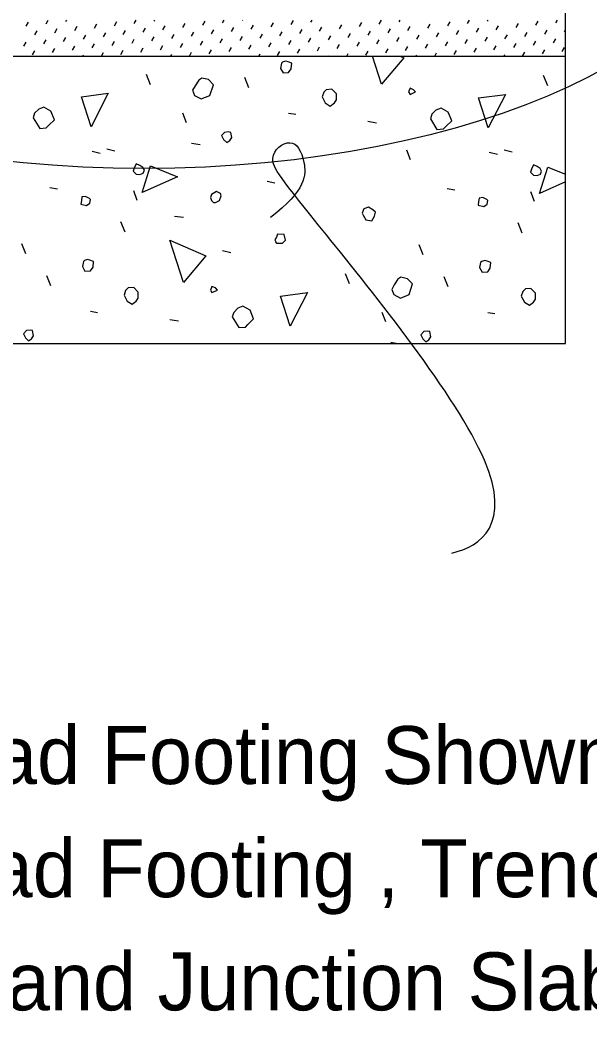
# Model space of a CAD drawing. Extents: x 120631.6 to 120706.2, y 120663.5 to 120716.4.
# Drawn here: x 120668.23 to 120670.212, y 120691.041 to 120694.546 of the extents above; entities that cross this region are included whole.
import ezdxf

# ---------------------------------------------------------------- set-up
doc = ezdxf.new("R2010")
doc.units = 0
for name, color, linetype in [('Dimension', 7, 'Continuous'), ('Miscellaneous', 7, 'Continuous'), ('TextStructures', 7, 'Continuous'), ('TrafBarrierConc', 7, 'Continuous')]:
    doc.layers.add(name, color=color, linetype=linetype)

msp = doc.modelspace()

# ---------------------------------------------------------------- linework, layer by layer
at = {"layer": 'Dimension'}
msp.add_ellipse((120668.6608, 120695.0005), major_axis=(2.0883, 0), ratio=0.464675, dxfattribs=at)
msp.add_open_spline([(120669.7314, 120692.6924), (120669.8349, 120692.715), (120670.0444, 120692.8737), (120669.1629, 120693.9627), (120669.0781, 120694.0699), (120669.1763, 120694.1458), (120669.2254, 120694.0654), (120669.2254, 120693.9538), (120669.1004, 120693.86)], degree=3, dxfattribs=at)
at = {"layer": 'Miscellaneous'}
for p, q in [((120668.2507, 120694.5249), (120668.2588, 120694.5389)), ((120668.3199, 120694.533), (120668.3274, 120694.546)), ((120668.389, 120694.5411), (120668.3919, 120694.546)), ((120668.4196, 120694.5106), (120668.4277, 120694.5246)), ((120668.4887, 120694.5187), (120668.4968, 120694.5327)), ((120668.5579, 120694.5268), (120668.566, 120694.5408)), ((120668.627, 120694.5349), (120668.6335, 120694.546)), ((120668.6962, 120694.543), (120668.698, 120694.546)), ((120668.7267, 120694.5124), (120668.7348, 120694.5264)), ((120668.7959, 120694.5205), (120668.804, 120694.5345)), ((120668.8651, 120694.5286), (120668.8732, 120694.5426)), ((120668.9342, 120694.5368), (120668.9396, 120694.546)), ((120668.9648, 120694.5062), (120668.9729, 120694.5202)), ((120669.0034, 120694.5449), (120669.0041, 120694.546)), ((120669.0339, 120694.5143), (120669.042, 120694.5283)), ((120669.1031, 120694.5224), (120669.1112, 120694.5364)), ((120669.1723, 120694.5305), (120669.1804, 120694.5445)), ((120669.2414, 120694.5386), (120669.2457, 120694.546)), ((120669.2719, 120694.5081), (120669.28, 120694.5221)), ((120669.3411, 120694.5162), (120669.3492, 120694.5302)), ((120669.4103, 120694.5243), (120669.4184, 120694.5383)), ((120669.4794, 120694.5324), (120669.4873, 120694.546)), ((120669.5486, 120694.5405), (120669.5518, 120694.546)), ((120669.5791, 120694.51), (120669.5872, 120694.524)), ((120669.6483, 120694.5181), (120669.6564, 120694.5321)), ((120669.7175, 120694.5262), (120669.7256, 120694.5402)), ((120669.7866, 120694.5343), (120669.7934, 120694.546)), ((120669.8558, 120694.5424), (120669.8579, 120694.546)), ((120669.8863, 120694.5119), (120669.8944, 120694.5258)), ((120669.9555, 120694.52), (120669.9636, 120694.534)), ((120670.0246, 120694.5281), (120670.0327, 120694.5421)), ((120670.0938, 120694.5362), (120670.0995, 120694.546)), ((120668.2812, 120694.4944), (120668.2893, 120694.5084)), ((120668.3504, 120694.5025), (120668.3585, 120694.5165)), ((120668.3809, 120694.4719), (120668.389, 120694.4859)), ((120668.4501, 120694.48), (120668.4582, 120694.494)), ((120668.5192, 120694.4881), (120668.5273, 120694.5021)), ((120668.5884, 120694.4962), (120668.5965, 120694.5102)), ((120668.6576, 120694.5043), (120668.6657, 120694.5183)), ((120668.6881, 120694.4738), (120668.6962, 120694.4878)), ((120668.7573, 120694.4819), (120668.7654, 120694.4959)), ((120668.8264, 120694.49), (120668.8345, 120694.504)), ((120668.8956, 120694.4981), (120668.9037, 120694.5121)), ((120668.9953, 120694.4757), (120669.0034, 120694.4897)), ((120669.0645, 120694.4838), (120669.0726, 120694.4978)), ((120669.1336, 120694.4919), (120669.1417, 120694.5059)), ((120669.2028, 120694.5), (120669.2109, 120694.514)), ((120669.3025, 120694.4776), (120669.3106, 120694.4916)), ((120669.3716, 120694.4857), (120669.3797, 120694.4997)), ((120669.4408, 120694.4938), (120669.4489, 120694.5078)), ((120669.51, 120694.5019), (120669.5181, 120694.5159)), ((120669.5405, 120694.4713), (120669.5486, 120694.4853)), ((120669.6097, 120694.4794), (120669.6178, 120694.4934)), ((120669.6788, 120694.4875), (120669.6869, 120694.5015)), ((120669.748, 120694.4957), (120669.7561, 120694.5096)), ((120669.8172, 120694.5038), (120669.8253, 120694.5177)), ((120669.8477, 120694.4732), (120669.8558, 120694.4872)), ((120669.9168, 120694.4813), (120669.925, 120694.4953)), ((120669.986, 120694.4894), (120669.9941, 120694.5034)), ((120670.0552, 120694.4975), (120670.0633, 120694.5115)), ((120670.1243, 120694.5056), (120670.1273, 120694.5107)), ((120668.2426, 120694.4557), (120668.2507, 120694.4697)), ((120668.3118, 120694.4638), (120668.3199, 120694.4778)), ((120668.4114, 120694.4414), (120668.4196, 120694.4554)), ((120668.4806, 120694.4495), (120668.4887, 120694.4635)), ((120668.5498, 120694.4576), (120668.5579, 120694.4716)), ((120668.6189, 120694.4657), (120668.627, 120694.4797)), ((120668.6495, 120694.4352), (120668.6576, 120694.4492)), ((120668.7186, 120694.4433), (120668.7267, 120694.4573)), ((120668.7878, 120694.4514), (120668.7959, 120694.4654)), ((120668.857, 120694.4595), (120668.8651, 120694.4735)), ((120668.9261, 120694.4676), (120668.9342, 120694.4816)), ((120668.9567, 120694.4371), (120668.9648, 120694.4511)), ((120669.0258, 120694.4452), (120669.0339, 120694.4592)), ((120669.095, 120694.4533), (120669.1031, 120694.4673)), ((120669.1641, 120694.4614), (120669.1723, 120694.4754)), ((120669.2333, 120694.4695), (120669.2414, 120694.4835)), ((120669.2638, 120694.4389), (120669.2719, 120694.4529)), ((120669.333, 120694.447), (120669.3411, 120694.461)), ((120669.4022, 120694.4551), (120669.4103, 120694.4691)), ((120669.4713, 120694.4632), (120669.4794, 120694.4772)), ((120669.571, 120694.4408), (120669.5791, 120694.4548)), ((120669.6402, 120694.4489), (120669.6483, 120694.4629)), ((120669.7094, 120694.457), (120669.7175, 120694.471)), ((120669.7785, 120694.4651), (120669.7866, 120694.4791)), ((120669.8782, 120694.4427), (120669.8863, 120694.4567)), ((120669.9474, 120694.4508), (120669.9555, 120694.4648)), ((120670.0165, 120694.4589), (120670.0246, 120694.4729)), ((120670.0857, 120694.467), (120670.0938, 120694.481)), ((120670.1162, 120694.4365), (120670.1243, 120694.4505)), ((120668.2731, 120694.4252), (120668.2812, 120694.4392)), ((120668.3423, 120694.4333), (120668.3504, 120694.4473)), ((120668.4478, 120694.421), (120668.4501, 120694.4249)), ((120668.5123, 120694.421), (120668.5192, 120694.433)), ((120668.5803, 120694.4271), (120668.5884, 120694.4411)), ((120668.7539, 120694.421), (120668.7573, 120694.4267)), ((120668.8184, 120694.421), (120668.8264, 120694.4348)), ((120668.8875, 120694.429), (120668.8956, 120694.4429)), ((120669.06, 120694.421), (120669.0645, 120694.4286)), ((120669.1255, 120694.4227), (120669.1336, 120694.4367)), ((120669.1947, 120694.4308), (120669.2028, 120694.4448)), ((120669.3017, 120694.421), (120669.3025, 120694.4224)), ((120669.3661, 120694.421), (120669.3716, 120694.4305)), ((120669.4327, 120694.4246), (120669.4408, 120694.4386)), ((120669.5019, 120694.4327), (120669.51, 120694.4467)), ((120669.6078, 120694.421), (120669.6097, 120694.4243)), ((120669.6722, 120694.421), (120669.6788, 120694.4324)), ((120669.7399, 120694.4265), (120669.748, 120694.4405)), ((120669.8091, 120694.4346), (120669.8172, 120694.4486)), ((120669.9139, 120694.421), (120669.9168, 120694.4262)), ((120669.9783, 120694.421), (120669.986, 120694.4343)), ((120670.0471, 120694.4284), (120670.0552, 120694.4424)), ((120668.6831, 120694.3216), (120668.6689, 120694.357)), ((120669.026, 120694.311), (120669.0119, 120694.3464)), ((120670.0655, 120694.3181), (120670.0513, 120694.3534)), ((120668.8086, 120694.189), (120668.7962, 120694.2226)), ((120669.1639, 120694.2226), (120669.1887, 120694.2191)), ((120669.4397, 120694.1943), (120669.4697, 120694.189)), ((120668.5311, 120694.0989), (120668.5593, 120694.0918)), ((120668.8263, 120694.1183), (120668.8563, 120694.113)), ((120668.4798, 120694.09), (120668.5081, 120694.083)), ((120669.5882, 120694.06), (120669.5758, 120694.0936)), ((120669.8622, 120694.0865), (120669.8905, 120694.0794)), ((120669.9135, 120694.0953), (120669.9417, 120694.0883)), ((120668.3331, 120693.9645), (120668.3596, 120693.9592)), ((120669.0897, 120693.9857), (120669.1162, 120693.9804)), ((120669.7155, 120693.961), (120669.742, 120693.9557)), ((120668.6371, 120693.9186), (120668.6248, 120693.9521)), ((120670.0195, 120693.915), (120670.0071, 120693.9486)), ((120668.7662, 120693.8638), (120668.798, 120693.8602)), ((120668.5947, 120693.809), (120668.5806, 120693.8443)), ((120669.9771, 120693.8054), (120669.963, 120693.8408)), ((120668.25, 120693.7329), (120668.2358, 120693.7683)), ((120669.6324, 120693.7294), (120669.6182, 120693.7648)), ((120668.9341, 120693.7453), (120668.9624, 120693.7382)), ((120668.3366, 120693.6216), (120668.3225, 120693.6569)), ((120669.3761, 120693.6286), (120669.3619, 120693.664)), ((120669.719, 120693.618), (120669.7049, 120693.6534)), ((120668.4745, 120693.5332), (120668.4992, 120693.5296)), ((120668.7503, 120693.5049), (120668.7803, 120693.4996)), ((120669.5016, 120693.4961), (120669.4892, 120693.5296)), ((120669.8569, 120693.5296), (120669.8816, 120693.5261)), ((120669.5192, 120693.4254), (120669.5438, 120693.421))]:
    msp.add_line(p, q, dxfattribs=at)
for points in [[(120669.4874, 120694.3234), (120669.4557, 120694.421)], [(120669.5521, 120694.421), (120669.5652, 120694.4153), (120669.4874, 120694.3234)], [(120669.1356, 120694.3782), (120669.1445, 120694.3623), (120669.1639, 120694.364), (120669.1728, 120694.3764), (120669.1745, 120694.3959), (120669.1622, 120694.4012), (120669.1533, 120694.4029), (120669.1427, 120694.3994), (120669.1392, 120694.3959), (120669.1356, 120694.3782)], [(120668.8369, 120694.2845), (120668.8599, 120694.2721), (120668.8899, 120694.2845), (120668.9023, 120694.3216), (120668.8846, 120694.3393), (120668.8616, 120694.3446), (120668.851, 120694.3375), (120668.8387, 120694.3181), (120668.8298, 120694.3022), (120668.8369, 120694.2845)], [(120669.5864, 120694.288), (120669.6059, 120694.2969), (120669.5988, 120694.3039), (120669.5864, 120694.3092), (120669.5811, 120694.2969), (120669.5864, 120694.288)], [(120668.4763, 120694.1749), (120668.4427, 120694.2792), (120668.5364, 120694.2916), (120668.4763, 120694.1749)], [(120669.2806, 120694.2792), (120669.2912, 120694.258), (120669.3089, 120694.2474), (120669.323, 120694.258), (120669.3301, 120694.2686), (120669.3301, 120694.2898), (120669.3142, 120694.3057), (120669.2947, 120694.3039), (120669.2859, 120694.2951), (120669.2806, 120694.2792)], [(120669.8587, 120694.1713), (120669.8251, 120694.2756), (120669.9188, 120694.288), (120669.8587, 120694.1713)], [(120668.2747, 120694.2067), (120668.2977, 120694.1696), (120668.3207, 120694.1713), (120668.3295, 120694.1802), (120668.349, 120694.1996), (120668.3366, 120694.2297), (120668.3119, 120694.2438), (120668.2942, 120694.2368), (120668.28, 120694.2226), (120668.2747, 120694.2067)], [(120669.6571, 120694.2032), (120669.6801, 120694.166), (120669.7031, 120694.1678), (120669.7119, 120694.1767), (120669.7314, 120694.1961), (120669.719, 120694.2261), (120669.6943, 120694.2403), (120669.6766, 120694.2332), (120669.6624, 120694.2191), (120669.6571, 120694.2032)], [(120668.9376, 120694.1307), (120668.9483, 120694.1201), (120668.9589, 120694.1272), (120668.9659, 120694.1378), (120668.9624, 120694.1554), (120668.9536, 120694.1572), (120668.9412, 120694.1554), (120668.9306, 120694.1448), (120668.9376, 120694.1307)], [(120668.6336, 120694.0105), (120668.646, 120694.0087), (120668.6583, 120694.014), (120668.6619, 120694.0246), (120668.6566, 120694.0335), (120668.646, 120694.0405), (120668.6336, 120694.0458), (120668.6265, 120694.0317), (120668.623, 120694.0211), (120668.6336, 120694.0105)], [(120668.6548, 120693.9468), (120668.6831, 120694.0388), (120668.7768, 120694.0016), (120668.6548, 120693.9468)], [(120670.016, 120694.0069), (120670.0284, 120694.0052), (120670.0407, 120694.0105), (120670.0443, 120694.0211), (120670.039, 120694.0299), (120670.0284, 120694.037), (120670.016, 120694.0423), (120670.0089, 120694.0282), (120670.0054, 120694.0176), (120670.016, 120694.0069)], [(120670.0372, 120693.9433), (120670.0655, 120694.0352), (120670.1273, 120694.0108)], [(120670.1273, 120693.9838), (120670.0372, 120693.9433)], [(120668.4409, 120693.9062), (120668.4604, 120693.9009), (120668.4727, 120693.9097), (120668.4745, 120693.9221), (120668.471, 120693.9256), (120668.4568, 120693.9327), (120668.4444, 120693.9309), (120668.4427, 120693.9186), (120668.4409, 120693.9062)], [(120668.9023, 120693.9115), (120668.9094, 120693.9115), (120668.9235, 120693.9186), (120668.9288, 120693.9345), (120668.927, 120693.9433), (120668.9129, 120693.9504), (120668.8952, 120693.9398), (120668.8917, 120693.9292), (120668.8952, 120693.9186), (120668.9023, 120693.9115)], [(120669.8233, 120693.9026), (120669.8427, 120693.8973), (120669.8551, 120693.9062), (120669.8569, 120693.9186), (120669.8534, 120693.9221), (120669.8392, 120693.9292), (120669.8268, 120693.9274), (120669.8251, 120693.915), (120669.8233, 120693.9026)], [(120669.4238, 120693.8673), (120669.4326, 120693.8514), (120669.4538, 120693.8478), (120669.4627, 120693.8638), (120669.4662, 120693.8779), (120669.4574, 120693.8867), (120669.4415, 120693.8956), (120669.4256, 120693.8903), (120669.4202, 120693.8744), (120669.4238, 120693.8673)], [(120669.1215, 120693.7701), (120669.1427, 120693.7701), (120669.1533, 120693.7807), (120669.148, 120693.8001), (120669.125, 120693.8019), (120669.1215, 120693.7913), (120669.1162, 120693.7824), (120669.1215, 120693.7701), (120669.118, 120693.7736)], [(120668.798, 120693.6339), (120668.7503, 120693.7807), (120668.8758, 120693.7259), (120668.798, 120693.6339)], [(120668.4462, 120693.6887), (120668.455, 120693.6728), (120668.4745, 120693.6746), (120668.4833, 120693.687), (120668.4851, 120693.7064), (120668.4727, 120693.7117), (120668.4639, 120693.7135), (120668.4533, 120693.71), (120668.4497, 120693.7064), (120668.4462, 120693.6887)], [(120669.8286, 120693.6852), (120669.8374, 120693.6693), (120669.8569, 120693.6711), (120669.8657, 120693.6834), (120669.8675, 120693.7029), (120669.8551, 120693.7082), (120669.8463, 120693.71), (120669.8357, 120693.7064), (120669.8321, 120693.7029), (120669.8286, 120693.6852)], [(120669.5299, 120693.5915), (120669.5528, 120693.5791), (120669.5829, 120693.5915), (120669.5953, 120693.6286), (120669.5776, 120693.6463), (120669.5546, 120693.6516), (120669.544, 120693.6446), (120669.5316, 120693.6251), (120669.5228, 120693.6092), (120669.5299, 120693.5915)], [(120668.5912, 120693.5898), (120668.6018, 120693.5685), (120668.6195, 120693.5579), (120668.6336, 120693.5685), (120668.6407, 120693.5791), (120668.6407, 120693.6004), (120668.6248, 120693.6163), (120668.6053, 120693.6145), (120668.5965, 120693.6057), (120668.5912, 120693.5898)], [(120668.897, 120693.5986), (120668.9164, 120693.6074), (120668.9094, 120693.6145), (120668.897, 120693.6198), (120668.8917, 120693.6074), (120668.897, 120693.5986)], [(120669.9736, 120693.5862), (120669.9842, 120693.565), (120670.0018, 120693.5544), (120670.016, 120693.565), (120670.0231, 120693.5756), (120670.0231, 120693.5968), (120670.0071, 120693.6127), (120669.9877, 120693.611), (120669.9789, 120693.6021), (120669.9736, 120693.5862)], [(120669.1692, 120693.4819), (120669.1356, 120693.5862), (120669.2293, 120693.5986), (120669.1692, 120693.4819)], [(120668.9677, 120693.5137), (120668.9907, 120693.4766), (120669.0137, 120693.4784), (120669.0225, 120693.4872), (120669.0419, 120693.5067), (120669.0296, 120693.5367), (120669.0048, 120693.5509), (120668.9871, 120693.5438), (120668.973, 120693.5296), (120668.9677, 120693.5137)], [(120668.2482, 120693.4413), (120668.2588, 120693.4307), (120668.2694, 120693.4377), (120668.2765, 120693.4483), (120668.273, 120693.466), (120668.2641, 120693.4678), (120668.2518, 120693.466), (120668.2411, 120693.4554), (120668.2482, 120693.4413)], [(120669.6306, 120693.4377), (120669.6412, 120693.4271), (120669.6518, 120693.4342), (120669.6589, 120693.4448), (120669.6554, 120693.4625), (120669.6465, 120693.4642), (120669.6341, 120693.4625), (120669.6235, 120693.4519), (120669.6306, 120693.4377)]]:
    msp.add_lwpolyline(points, dxfattribs=at)
at = {"layer": 'TrafBarrierConc'}
for p, q in [((120670.1273, 120693.4211), (120670.1273, 120702.4835)), ((120654.2962, 120694.421), (120670.1273, 120694.421)), ((120654.2962, 120693.4211), (120670.1273, 120693.4211))]:
    msp.add_line(p, q, dxfattribs=at)

# ---------------------------------------------------------------- texts
at = {"layer": 'TextStructures'}
for s, p in [('T-Shaped Spread Footing Shown, ', (120666.3103, 120691.8889)), ('L-Shaped Spread Footing , Trench ', (120666.3103, 120691.4953)), ('Footing Similar and Junction Slab similar', (120666.3103, 120691.1017))]:
    msp.add_text(s, height=0.2016, dxfattribs=at).set_placement(p)

doc.saveas('drawing.dxf')
